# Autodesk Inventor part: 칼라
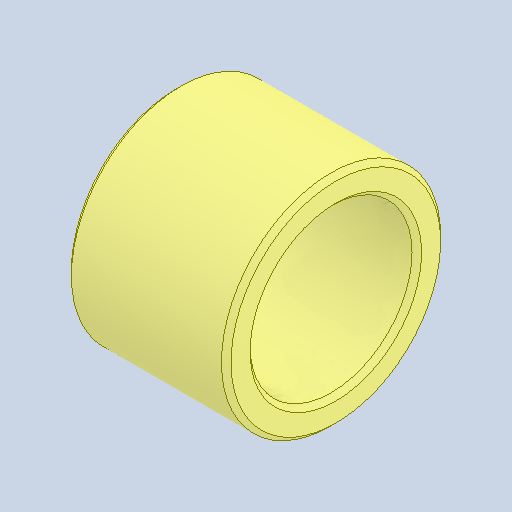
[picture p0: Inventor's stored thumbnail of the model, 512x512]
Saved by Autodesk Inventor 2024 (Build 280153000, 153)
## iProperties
Created: 2026-01
Part Number: 칼라
Material: 강철, 연강
Document SubType Name: Modeling
Designer: 2-10
Density: 7.85 g/cm^3
Appearance: 기본값
Sending System: Autodesk Inventor 2026
Preprocessor: ST-DEVELOPER v20.1
Author: jhkim
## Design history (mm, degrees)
node "칼라1"
node "솔리드2"
node "솔리드1"
